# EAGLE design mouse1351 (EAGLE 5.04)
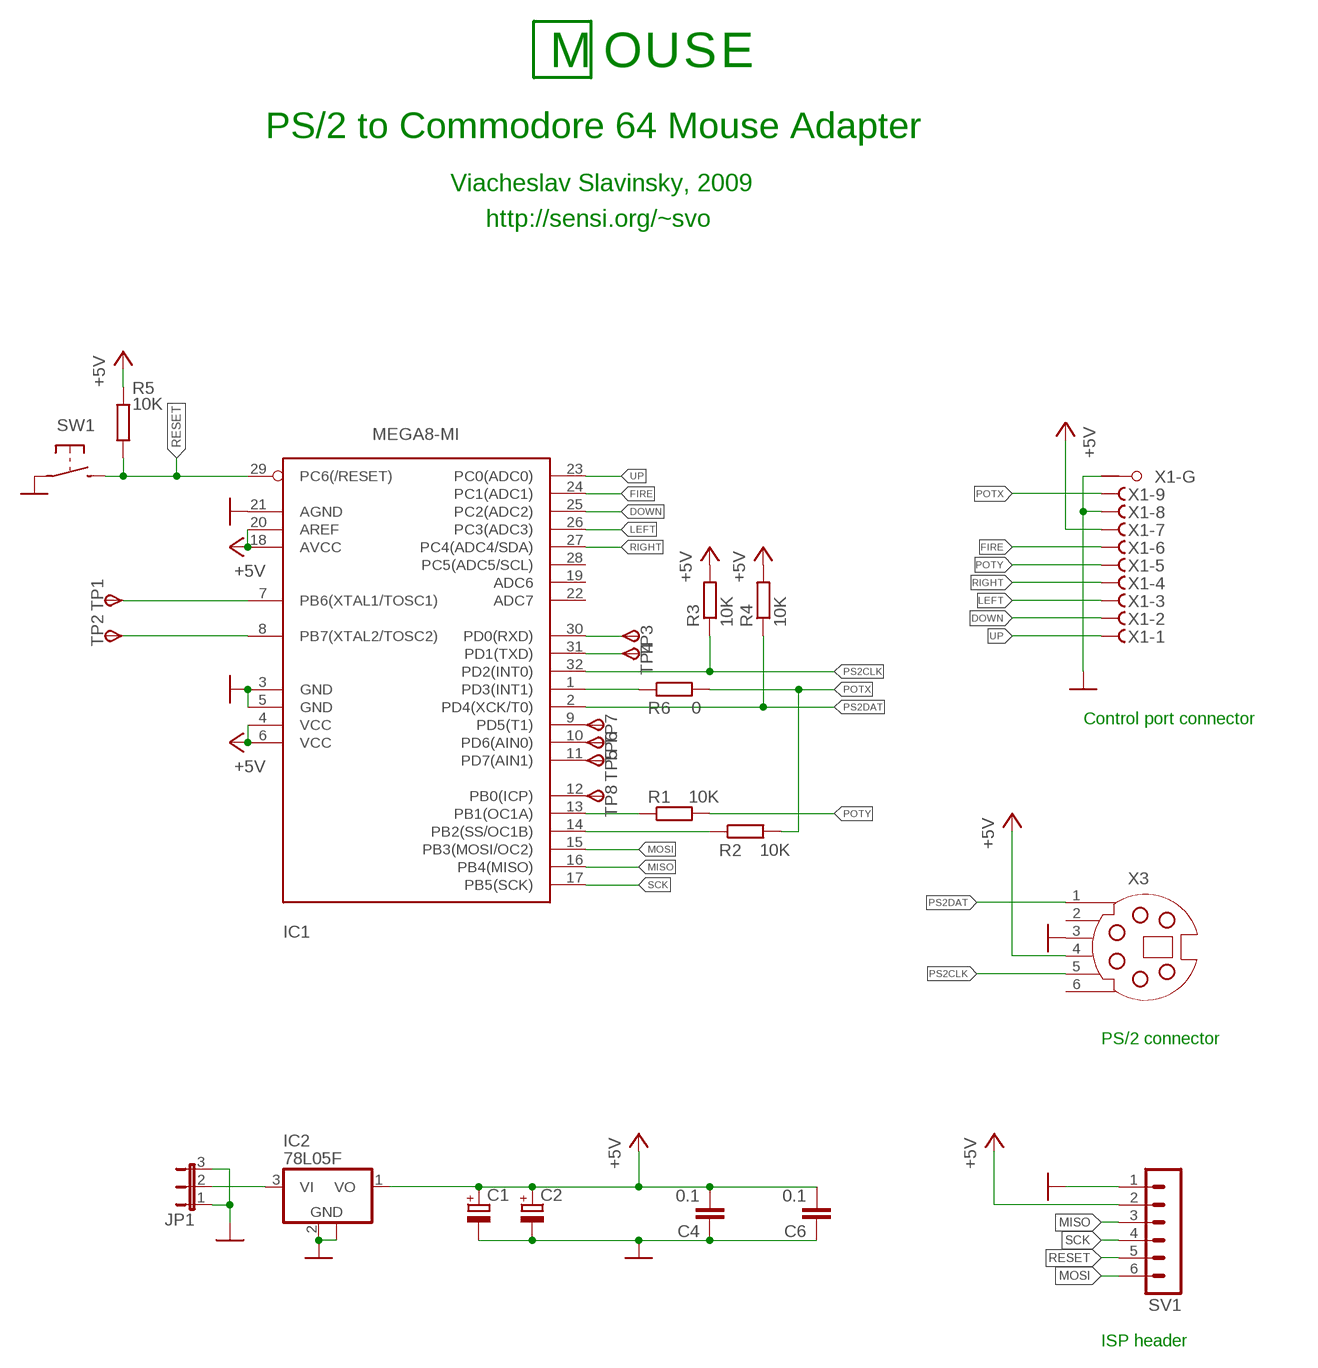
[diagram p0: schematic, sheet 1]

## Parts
C1  CPOL-EUSMCC  [SMC_C]
C2  CPOL-EUSMCC  [SMC_C]
C4  0.1  C-EUC0603K  [C0603K]
C6  0.1  C-EUC0603K  [C0603K]
IC1  MEGA8-MI  [MLF32]
IC2  78L05F  [SOT89]
JP1  JP2W  [JP2W]
R1  10K  R-EU_R0805  [R0805]
R2  10K  R-EU_R0805  [R0805]
R3  10K  R-EU_R0805  [R0805]
R4  10K  R-EU_R0805  [R0805]
R5  10K  R-EU_R0805  [R0805]
R6  0  R-EU_R0805  [R0805]
SV1  MA06-1  [MA06-1]
SW1  BUTTON-IT_1181  [SW_IT1181]
TP1  TPSTP06R  [TP06R]
TP2  TPSTP06R  [TP06R]
TP3  TPSTP10R  [TP10R]
TP4  TPSTP10R  [TP10R]
TP5  TPSTP06R  [TP06R]
TP6  TPSTP06R  [TP06R]
TP7  TPSTP06R  [TP06R]
TP8  TPSTP06R  [TP06R]
X1  F09HPS  [F09HP]
X3  SSV-G06  [SSV-BC06]

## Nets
+5V: C1.+ C2.+ C4.2 C6.2 IC1.4(VCC) IC1.6(VCC) IC1.18(AVCC) IC1.20(AREF) IC2.1(VO) R3.2 R4.2 R5.2 SV1.2 X1.7(-7:F) X3.4
DOWN: IC1.25(PC2(ADC2)) X1.2(-2:F)
FIRE: IC1.24(PC1(ADC1)) X1.6(-6:F)
GND: C1.- C2.- C4.1 C6.1 IC1.3(GND) IC1.5(GND) IC1.21(AGND) IC2.2(GND) IC2.2@1(GND) JP1.1 JP1.3 SV1.1 SW1.P$1(P1) X1.8(-8:F) X1.G1(-G:G1) X3.3
LEFT: IC1.26(PC3(ADC3)) X1.3(-3:F)
MISO: IC1.16(PB4(MISO)) SV1.3
MOSI: IC1.15(PB3(MOSI/OC2)) SV1.6
N$1: IC1.1(PD3(INT1)) R6.1
N$2: IC1.7(PB6(XTAL1/TOSC1)) TP1.TP(PP)
N$3: IC1.8(PB7(XTAL2/TOSC2)) TP2.TP(PP)
N$4: IC1.13(PB1(OC1A)) R1.1
N$5: IC1.14(PB2(SS/OC1B)) R2.1
N$6: IC2.3(VI) JP1.2
N$8: IC1.11(PD7(AIN1)) TP5.TP(PP)
N$9: IC1.10(PD6(AIN0)) TP6.TP(PP)
N$10: IC1.9(PD5(T1)) TP7.TP(PP)
N$11: IC1.12(PB0(ICP)) TP8.TP(PP)
POTX: R2.2 R6.2 X1.9(-9:F)
POTY: R1.2 X1.5(-5:F)
PS2CLK: IC1.32(PD2(INT0)) R3.1 X3.5
PS2DAT: IC1.2(PD4(XCK/T0)) R4.1 X3.1
RESET: IC1.29(PC6(/RESET)) R5.1 SV1.5 SW1.P$2(P2)
RIGHT: IC1.27(PC4(ADC4/SDA)) X1.4(-4:F)
RXD: IC1.30(PD0(RXD)) TP3.TP(PP)
SCK: IC1.17(PB5(SCK)) SV1.4
TXD: IC1.31(PD1(TXD)) TP4.TP(PP)
UP: IC1.23(PC0(ADC0)) X1.1(-1:F)
Unconnected: IC1.19(ADC6) IC1.22(ADC7) IC1.28(PC5(ADC5/SCL)) X1.G2(-G:G2) X3.2 X3.6

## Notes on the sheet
- M | O | U | S | E
- PS/2 to Commodore 64 Mouse Adapter
- Viacheslav Slavinsky, 2009
- http://sensi.org/~svo
- Control port connector
- PS/2 connector
- ISP header

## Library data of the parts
C1 C2 = rcl:CPOL-EU: POLARIZED CAPACITOR, European symbol
C4 C6 = rcl:C-EU: CAPACITOR, European symbol
IC1 = atmel:MEGA8: MICROCONTROLLER 8 Kbytes FLASH, 1 kbytes SRAM, 512 bytes EEPROM, USART, 6-channel 10 bit ADC, 2-channel 8 bit ADC Pin compatible with Atmega48, ATMega88, ATMega168 Source: avr.lbr
IC2 = linear:78L*: POSITOIV-VOLTAGE REGULATORS Output up to 100 mA Source: http://focus.ti.com/lit/ds/symlink/ua78l05.pdf
JP1 = jumper:JP2W: JUMPER
R1-R6 = rcl:R-EU_: RESISTOR, European symbol
SV1 = con-lstb:MA06-1: PIN HEADER
SW1 = 0-svo:BUTTON-IT_1181
TP1-TP8 = 0-svo:TPS: TEST PIN
X1 = con-subd:F09HPS: SUB-D
X3 = con-yamaichi:SSV-G06: YAMAICHI CONNECTOR

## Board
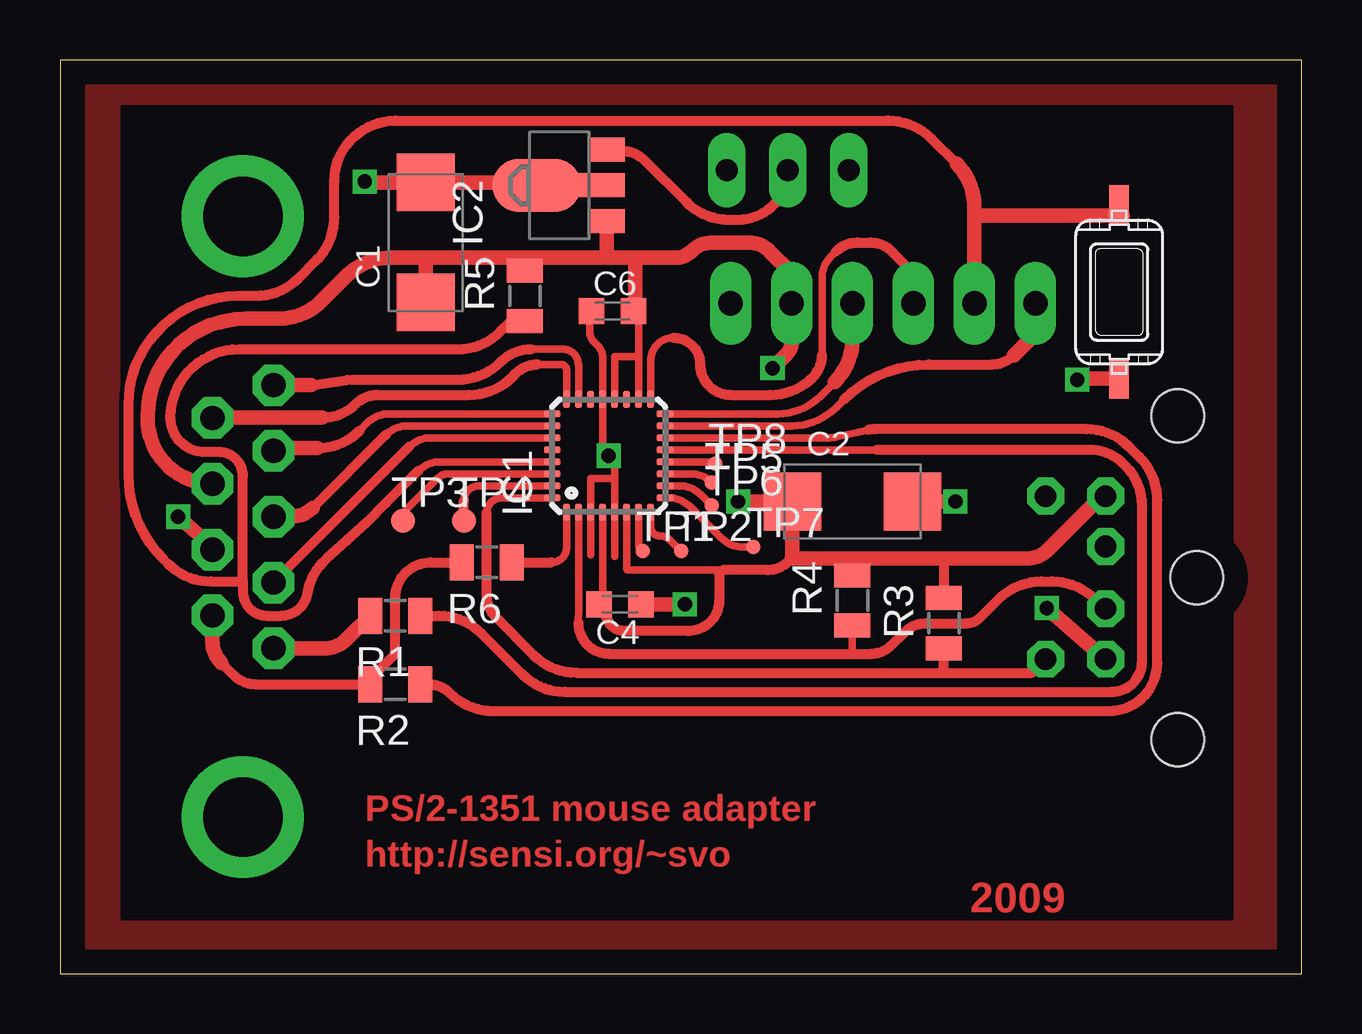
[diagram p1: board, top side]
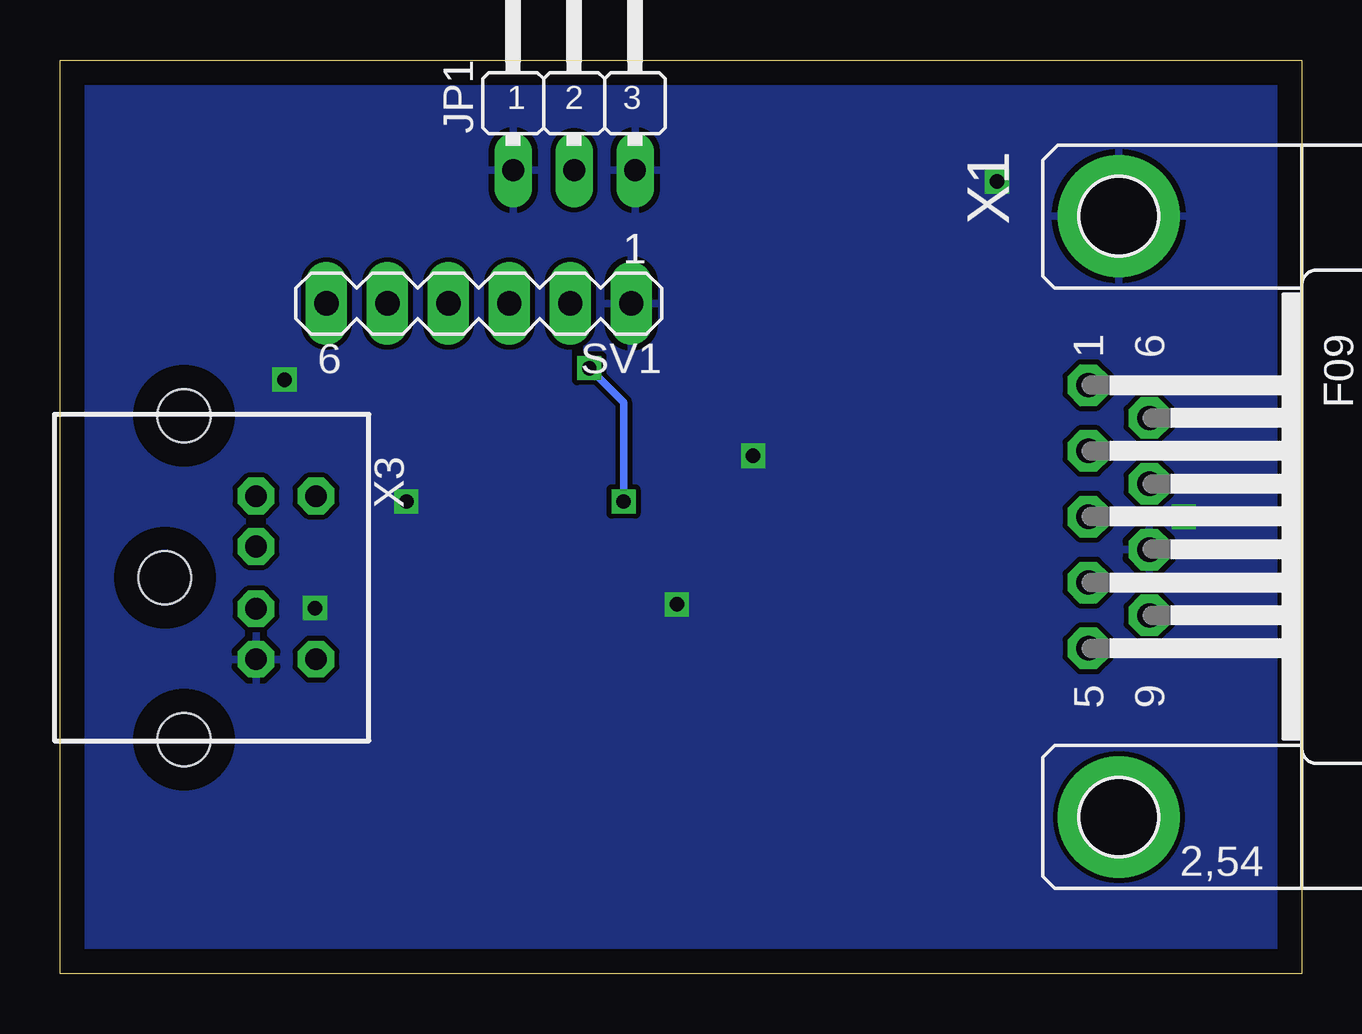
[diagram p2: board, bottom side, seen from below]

Size 51.74 x 38.09 mm. Coordinates in mm from the lower left corner, seen from the top.
Outline: 0,0 51.74,0 51.74,38.09 0,38.09 0,0
Copper layers (1*16): Top 0.035mm / dielectric 1.5mm / Bottom 0.035mm
Design rules "default *": minimum track width 10mil, minimum drill 24mil, track to track 8mil, track to pad 8mil, pad to pad 8mil, via to via 8mil, smd to smd 8mil, copper to edge 40mil, drill to drill 8mil, minimum pad ring 10mil, minimum via ring 8mil, stop-mask expansion 4mil, vias tented up to drill 0mil, thermal gap 10mil
tRestrict: area 2.5,2.9 to 48.9,36.2; area 2.5,2.2 to 48.9,2.9

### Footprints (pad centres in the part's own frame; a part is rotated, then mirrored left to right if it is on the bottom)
SMC_C = smd 2.4 x 2.4: + -2.5,0; - 2.5,0
C0603K = smd 1.05 x 1.08: 1 -0.875,0; 2 0.875,0
MLF32 = smd 0.7 x 0.3: 1 -2.35,1.75; 2 -2.35,1.25; 3 -2.35,0.75; 4 -2.35,0.25; 5 -2.35,-0.25; 6 -2.35,-0.75; 7 -2.35,-1.25; 8 -2.35,-1.75; 17 2.35,-1.75; 18 2.35,-1.25; 19 2.35,-0.75; 20 2.35,-0.25; 21 2.35,0.25; 22 2.35,0.75; 23 2.35,1.25; 24 2.35,1.75 | smd 0.3 x 0.7: 9 -1.75,-2.35; 10 -1.25,-2.35; 11 -0.75,-2.35; 12 -0.25,-2.35; 13 0.25,-2.35; 14 0.75,-2.35; 15 1.25,-2.35; 16 1.75,-2.35; 25 1.75,2.35; 26 1.25,2.35; 27 0.75,2.35; 28 0.25,2.35; 29 -0.25,2.35; 30 -0.75,2.35; 31 -1.25,2.35; 32 -1.75,2.35
SOT89 = smd 1 x 1.5: 1 -1.499,-1.981; 3 1.499,-1.981 | smd 1 x 2: 2 0,-1.727 | smd 2.2 x 3.7: 2@1 0,0.94
JP2W = drill 0.914 long: 1 -2.54,-1.27; 2 0,-1.27; 3 2.54,-1.27
R0805 = smd 1 x 1.5: 1 -1.05,0; 2 1.05,0
MA06-1 = drill 1.016 long: 1 -6.35,0; 2 -3.81,0; 3 -1.27,0; 4 1.27,0; 5 3.81,0; 6 6.35,0
SW_IT1181 = smd 1.676 x 0.813: P$1 -3.61,0; P$2 3.61,0
TP06R = smd 0.6 x 0.6: TP 0,0
TP10R = smd 1 x 1: TP 0,0
F09HP = drill 1.016 octagon: 1 -5.486,-1.27; 2 -2.743,-1.27; 3 0,-1.27; 4 2.743,-1.27; 5 5.486,-1.27; 6 -4.115,1.27; 7 -1.372,1.27; 8 1.372,1.27; 9 4.115,1.27 | drill 3.302 pad 5.08 round: G1 -12.522,0; G2 12.522,0
SSV-BC06 = drill 0.9 octagon: 1 1.3,8.5; 2 -1.3,8.5; 3 3.4,8.5; 4 -3.4,8.5; 5 3.4,11; 6 -3.4,11 | hole 2.2: -6.75,5.5; 0,4.7; 6.75,5.5

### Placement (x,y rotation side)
C1  15.24,30.48 90 top
C2  33.02,19.68 0 top
C4  23.34,15.4 180 top
C6  23.02,27.62 0 top
IC1  22.86,21.59 90 top
IC2  20.8,32.86 90 top
JP1  30.32,34.77 0 bottom
R1  13.97,14.92 180 top
R2  13.97,12.06 180 top
R3  36.83,14.61 90 top
R4  33.02,15.56 90 top
R5  19.37,28.26 90 top
R6  17.78,17.14 180 top
SV1  34.29,27.94 180 bottom
SW1  44.13,28.42 90 top
TP1  24.29,17.62 0 top
TP2  25.88,17.62 0 top
TP3  14.29,18.89 0 top
TP4  16.83,18.89 0 top
TP5  27.15,20.48 0 top
TP6  27.15,19.53 0 top
TP7  28.89,17.78 0 top
TP8  27.3,21.27 0 top
X1  7.62,19.05 270 bottom
X3  52.07,16.51 270 bottom

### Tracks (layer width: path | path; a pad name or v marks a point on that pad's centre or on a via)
+5V  (via drill 0.6)
  Top 0.305: IC1.20 23.11,25.72 24.11,25.72 | 24.11,25.72 IC1.18 | 24.13,27.62 C6.2 24.11,27.41 24.11,25.72 | IC1.4 22.61,15.73 C4.2 | R4.2 33.02,17.14 32.86,17.3 | 36.99,17.3 36.83,17.14 | 30.48,17.3 30.38,17.2 | 27.46,16.67 27.62,16.83 23.65,16.83 arc-45 23.61,16.93 IC1.6
  Top 0.406: C4.2 22.94,14.53 arc45 23.52,14.29 26.19,14.29 arc90 27.46,15.56 27.46,16.67 | 36.83,17.14 R3.2 | 30.38,17.2 arc-45 29.48,16.83 27.62,16.83
  Top 0.61: X3.4 43.41,19.91 41.17,17.68 arc-45 40.27,17.3 36.99,17.3 32.86,17.3 30.48,17.3 30.52,17.34 C2.+ v28.26,19.68 | 23.97,29.84 23.97,29.37 23.97,27.7 C6.2 | 15.4,29.84 19.05,29.84 | 19.05,29.84 22.86,29.84 | 22.86,29.84 23.97,29.84 | 19.05,29.84 R5.2 | C1.+ 15.24,29.69 15.4,29.84 | v29.69,25.24 30.29,25.85 arc45 30.48,26.3 SV1.2 30.48,29.21 29.58,30.11 arc45 28.68,30.48 27.2,30.48 arc45 26.3,30.11 arc-45 25.66,29.84 23.97,29.84 | 15.4,29.84 13.75,29.84 arc45 11.96,29.1 10.9,28.05 arc-45 9.11,27.3 7.72,27.3 arc90 3.65,23.24 3.65,23.12 arc90 X1.7 | IC2.1 22.78,30.05 arc45 22.86,29.84
  Bottom 0.305: v28.26,19.68 28.26,23.81 v29.69,25.24
DOWN
  Top 0.305: IC1.25 13.71,23.34 arc45 12.81,22.97 12.48,22.64 | X1.2 9,21.91
  Top 0.406: 10.71,21.91 arc45 12.48,22.64
  Top 0.61: 9,21.91 10.71,21.91
FIRE
  Top 0.305: X1.6 6.36,23.18 | IC1.24 21.11,25.15 arc90 20.86,25.4 19.89,25.4
  Top 0.406: 10.93,23.18 arc45 12.33,23.76 arc-45 13.23,24.13 17.05,24.13 arc45 18.84,24.87 19,25.03 arc-45 19.89,25.4
  Top 0.61: 6.36,23.18 10.93,23.18
GND  (via drill 0.6)
  Top 0.305: 22.11,17.46 IC1.3 22.11,20.64 23.11,20.64 | C6.1 22.07,27.55 22.07,26.77 arc45 22.25,26.32 22.42,26.15 arc-45 22.61,25.7 IC1.21 22.61,21.59 v22.86,21.59 23.11,21.34 23.11,20.64 | v42.39,24.77 42.43,24.81 | 23.11,17.39 IC1.5 23.11,20.64
  Top 0.61: 42.43,24.81 SW1.P$1 | v12.7,33.02 12.82,32.98 C1.- 21.59,32.98 | C2.- v37.31,19.68 | C4.1 v26.04,15.4 | 21.59,32.98 22.41,32.98 IC2.2 | IC2.2@1 21.47,32.86 21.59,32.98 | v4.92,19.05 6.35,17.78 | v41.12,15.24 43.66,13.02 43.66,13.18
  pour Bottom: 0,0 51.75,0 51.75,38.1 0,38.1
  pour Top: 21.75,22.7 21.75,20.48 23.97,20.48 23.97,22.7
LEFT
  Top 0.305: 13.58,22.47 arc-45 14.48,22.84 IC1.26
  Top 0.406: 10.53,19.42 13.58,22.47
  Top 0.61: X1.3 9.63,19.05 arc45 10.53,19.42
MISO
  Top 0.305: IC1.16 29.91,23.34 arc45 31.7,24.08 32.28,24.66
  Top 0.61: 32.28,24.66 arc45 33.02,26.45 SV1.3
MOSI
  Top 0.305: IC1.15 30.52,22.84 arc45 32.31,23.58 32.67,23.94
  Top 0.406: 32.67,23.94 arc-45 36.2,25.4 38.84,25.4 arc45 39.74,25.77
  Top 0.61: SV1.6 40.64,26.67 39.74,25.77
N$1
  Top 0.305: IC1.1 21.11,17.78 arc-90 20.48,17.14
  Top 0.406: R6.1 20.48,17.14
N$2
  Top 0.305: IC1.7 24.11,17.8 TP1.TP
N$3
  Top 0.305: TP2.TP 25.43,18.07 arc45 24.98,18.25 arc-90 24.61,18.62 IC1.8
N$4
  Top 0.305: 44.41,21.15 44.31,21.25 | 34.04,21.84 IC1.13
  Top 0.406: R1.1 15.79,14.92 arc-45 17.56,14.19 19.27,12.48 arc45 21.04,11.75 43.81,11.75 arc90 45.09,13.02 45.09,19.53 arc45 44.41,21.15 | 44.31,21.25 arc45 42.9,21.84 34.04,21.84
N$5
  Top 0.305: R2.1 15.35,12.06 | 16.25,11.69 | IC1.14 32.04,22.34 arc12 32.32,22.37 33.68,22.67
  Top 0.406: 15.35,12.06 arc-45 16.25,11.69 | 16.25,11.69 arc45 18.02,10.95 43.72,10.95 arc90 45.72,12.95 45.72,19.74 arc45 44.98,21.54 44.56,21.96 arc45 42.76,22.7 33.95,22.7 arc12 33.68,22.67
N$6
  Top 0.406: JP1.2 arc-90 28.26,31.43 27.88,31.43 arc-45 26.09,32.18 24.34,33.92 arc45 23.45,34.29 22.85,34.29 IC2.3
N$7
  pour Top: 0,38.1 51.75,38.1 51.75,0 0,0
N$8
  Top 0.305: IC1.11 26.27,20.84 arc-45 TP5.TP
N$9
  Top 0.305: TP6.TP 26.7,19.97 arc45 25.81,20.34 IC1.10
N$10
  Top 0.305: IC1.9 25.35,19.84 arc-45 26.25,19.47 27.57,18.15 arc45 28.47,17.78 TP7.TP
N$11
  Top 0.305: IC1.12 27.24,21.34 TP8.TP
POTX
  Top 0.305: R2.2 12.92,12.29
  Top 0.406: 6.72,12.96 7.25,12.44 arc45 8.15,12.06 R2.2 | 12.92,12.29 13.97,13.34 13.97,15.67 arc-90 15.45,17.14 R6.2
  Top 0.61: X1.9 6.35,13.86 arc45 6.72,12.96
POTY
  Top 0.61: X1.5 11.04,13.56 arc45 11.93,13.94 R1.2
PS2CLK
  Top 0.305: 36.67,12.54 36.83,12.7 | IC1.32 18.41,19.84 arc90 17.78,19.2
  Top 0.406: X3.5 40.5,12.54 36.67,12.54 21.51,12.54 arc-45 19.75,13.27 18.15,14.87 arc-45 17.78,15.77 17.78,19.2 | 36.83,12.7 R3.1
PS2DAT
  Top 0.305: IC1.2 21.61,15.26 21.6,14.63 | 33.02,13.34 R4.1
  Top 0.406: 21.6,14.63 arc91 22.87,13.34 33.02,13.34 33.76,13.34 arc45 34.66,13.71 35.19,14.23 arc-45 36.09,14.61 37.77,14.61 arc45 38.33,14.84 39.1,15.61 arc-45 40.9,16.35 41.33,16.35 arc-45 43.13,15.61 43.5,15.24 arc45 X3.1
RESET
  Top 0.305: 14.94,20.97 arc-45 15.83,21.34 IC1.29 | 4.5,17.09 4.32,17.27
  Top 0.406: 18.35,26.77 arc-45 16.59,26.04 7.46,26.04 arc90 4.6,23.18 arc90 6.03,21.75 6.62,21.75 arc-90 7.62,20.75 7.62,16.35 | 7.62,16.35 7.62,15.92 arc90 8.62,14.92 9.21,14.92 arc81 10.32,15.88 arc-41 11.11,17.3 arc5 13.58,19.61 14.94,20.97 | 4.5,17.09 arc45 6.29,16.35 7.62,16.35 | 4.32,17.27 arc-45 2.86,20.8 2.86,23.71 arc-90 7.4,28.26 8.15,28.26 arc45 9.95,29 10.69,29.74 arc45 11.43,31.53 11.43,33.02 arc-90 13.97,35.56 34.51,35.56 arc-45 36.3,34.82 37.36,33.76 | 18.35,26.77 | 18.35,26.77 18.73,27.15 19.31,27.15 R5.1 | 44.29,31.59 44.29,31.64 arc45 SW1.P$2
  Top 0.61: 38.1,31.59 SV1.5 | 38.1,31.59 44.29,31.59 | 37.36,33.76 arc-45 38.1,31.97 38.1,31.59
RIGHT
  Top 0.305: 14.55,21.97 arc-45 15.45,22.34 IC1.27
  Top 0.406: X1.4 14.55,21.97
RXD
  Top 0.305: TP3.TP arc-45 14.51,19.43 15.73,20.65 arc-45 16.18,20.84 IC1.30
SCK
  Top 0.305: 31.75,25.77 31.75,29 arc-45 32.12,29.9 32.33,30.11 | IC1.17 24.61,25.56 arc-90 25.56,26.51
  Top 0.406: SV1.4 35.56,29.21 34.66,30.11 arc45 33.76,30.48 33.23,30.48 arc45 32.33,30.11 | 31.75,25.77 arc-45 31.38,24.87 arc-45 29.59,24.13 27.94,24.13 arc-90 26.67,25.4 arc90 25.56,26.51
TXD
  Top 0.305: 16.83,19.7 arc-90 17.46,20.34 IC1.31
  Top 0.406: TP4.TP 16.83,19.7
UP
  Top 0.305: IC1.23 21.61,25.38 21.59,25.4 arc90 20.95,26.04 19.64,26.04 | 10.47,24.54 arc9 10.66,24.55 | 11.97,24.75 arc-9 12.16,24.77
  Top 0.406: 10.66,24.55 11.97,24.75 | 12.16,24.77 16.57,24.77 arc45 18.36,25.51 arc-45 19.64,26.04
  Top 0.61: X1.1 10.47,24.54

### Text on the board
Top: PS/2-1351 mouse adapter | http://sensi.org/~svo | 2009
